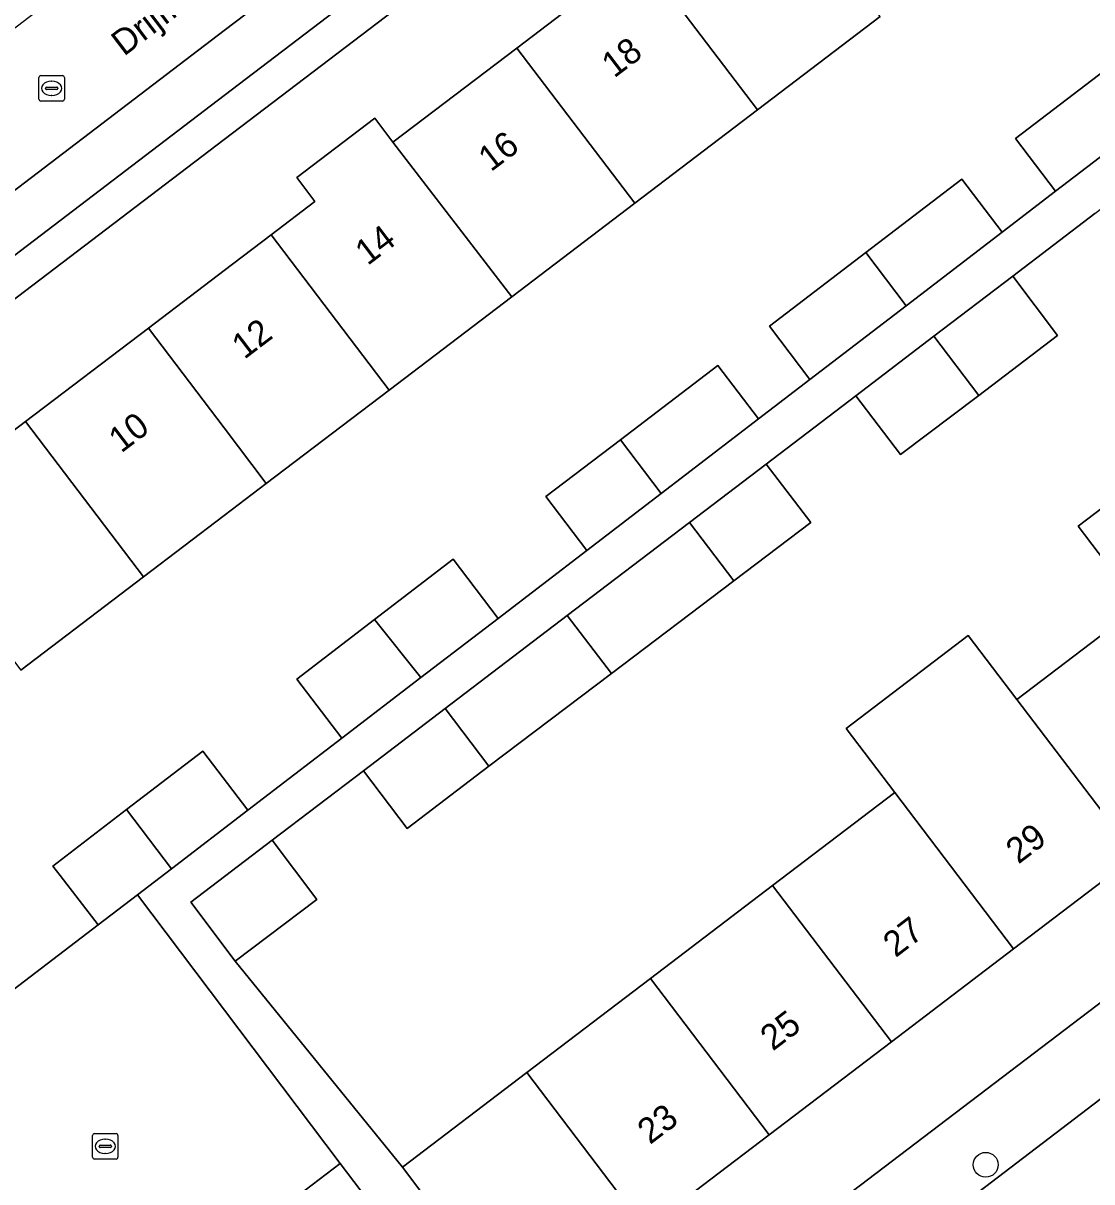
# Model space of a CAD drawing. Extents: x 160030 to 160839, y 385325 to 386450.
# Drawn here: x 160492.09 to 160534.15, y 385571 to 385616.57 of the extents above; entities that cross this region are included whole.
import ezdxf

# ---------------------------------------------------------------- set-up
doc = ezdxf.new("R2010")
doc.units = 0
for name, color, linetype in [('IMGEO_Boom', 7, 'Continuous'), ('IMGEO_Erf', 7, 'Continuous'), ('IMGEO_Kolk', 7, 'Continuous'), ('IMGEO_Openbare_ruimte_label', 7, 'Continuous'), ('IMGEO_Pand', 7, 'Continuous'), ('IMGEO_Pand_nummerreeks', 7, 'Continuous'), ('IMGEO_Parkeervlak_open', 7, 'Continuous'), ('IMGEO_Rijbaan_lokaal_open', 7, 'Continuous'), ('IMGEO_Rioolput', 7, 'Continuous'), ('IMGEO_Voetpad_open', 7, 'Continuous')]:
    doc.layers.add(name, color=color, linetype=linetype)

msp = doc.modelspace()

# ---------------------------------------------------------------- linework, layer by layer
at = {"layer": 'IMGEO_Boom'}
msp.add_circle((160529.975, 385571.672), 0.489, dxfattribs=at)
at = {"layer": 'IMGEO_Erf'}
for points in [[(160541.325, 385643.407), (160500, 385611.993), (160469.864, 385589.083), (160469.192, 385588.563), (160476.184, 385579.322), (160477.257, 385580.137), (160472.72, 385586.106), (160477.69, 385589.884), (160482.522, 385593.557), (160487.355, 385597.231), (160492.187, 385600.904), (160497.019, 385604.577), (160500, 385606.843), (160501.851, 385608.25), (160503.572, 385609.559), (160502.858, 385610.499)], [(160502.858, 385610.499), (160505.931, 385612.834), (160506.645, 385611.894), (160511.516, 385615.597), (160516.348, 385619.269), (160521.179, 385622.942), (160526.011, 385626.615), (160530.844, 385630.288), (160535.676, 385633.961), (160540.508, 385637.635), (160545.479, 385641.413), (160544.268, 385643.006)], [(160525.822, 385616.835), (160520.99, 385613.162), (160516.159, 385609.489), (160511.325, 385605.815), (160506.493, 385602.142), (160501.661, 385598.469), (160500, 385597.206), (160496.829, 385594.796), (160491.998, 385591.123)], [(160482.263, 385571.356), (160495.041, 385581.104), (160493.552, 385583.047), (160493.265, 385583.423), (160496.164, 385585.643), (160499.159, 385587.937), (160500.935, 385585.618), (160504.634, 385588.451), (160502.866, 385590.777), (160505.923, 385593.12), (160509.014, 385595.487), (160510.782, 385593.16), (160514.273, 385595.834), (160512.66, 385597.951), (160515.599, 385600.191), (160519.43, 385603.113), (160521.029, 385601.009), (160523.056, 385602.561), (160521.461, 385604.66), (160525.254, 385607.552), (160529.039, 385610.438), (160530.622, 385608.356), (160532.724, 385609.966), (160531.145, 385612.043), (160534.909, 385614.912)], [(160570.612, 385608.202), (160569.688, 385609.54), (160564.787, 385605.812), (160559.929, 385602.117), (160555.119, 385598.458), (160550.31, 385594.8), (160545.5, 385591.141), (160540.691, 385587.483), (160535.881, 385583.825), (160531.071, 385580.166), (160526.262, 385576.508), (160521.452, 385572.849), (160516.589, 385569.15), (160511.694, 385565.427), (160512.156, 385564.786)], [(160534.274, 385609.084), (160531.036, 385606.619), (160532.803, 385604.284), (160529.7, 385601.935), (160526.619, 385599.603), (160524.859, 385601.917), (160521.334, 385599.235), (160523.087, 385596.929), (160520.062, 385594.64), (160515.244, 385590.994), (160510.425, 385587.346), (160507.199, 385584.905), (160505.485, 385587.171), (160501.891, 385584.435), (160503.652, 385582.103), (160500.441, 385579.678), (160507.017, 385571.576), (160511.909, 385575.297), (160516.775, 385578.998), (160521.585, 385582.657), (160526.394, 385586.315), (160524.478, 385588.835), (160529.288, 385592.493), (160531.204, 385589.974), (160536.014, 385593.633), (160533.612, 385596.792), (160538.421, 385600.449)], [(160516.064, 385564.038), (160542.084, 385583.823), (160548.164, 385588.386)]]:
    msp.add_lwpolyline(points, dxfattribs=at)
at = {"layer": 'IMGEO_Kolk'}
for p, q in [((160494.823, 385571.974), (160494.823, 385572.826)), ((160494.898, 385572.9), (160495.75, 385572.9)), ((160495.311, 385572.68), (160495.336, 385572.68)), ((160495.824, 385572.826), (160495.824, 385571.974)), ((160495.082, 385572.394), (160495.082, 385572.406)), ((160495.52, 385572.357), (160495.122, 385572.357)), ((160495.125, 385572.443), (160495.523, 385572.443)), ((160495.566, 385572.406), (160495.566, 385572.394)), ((160495.75, 385571.9), (160494.898, 385571.9)), ((160495.334, 385572.12), (160495.309, 385572.12))]:
    msp.add_line(p, q, dxfattribs=at)
for points in [[(160494.823, 385571.974), (160494.823, 385572.826)], [(160494.898, 385572.9), (160495.75, 385572.9)], [(160495.824, 385572.826), (160495.824, 385571.974)], [(160495.75, 385571.9), (160494.898, 385571.9)]]:
    msp.add_lwpolyline(points, dxfattribs=at)
for centre, radius, start, end in [((160494.9, 385572.824), 0.0765, 91.552, 178.448), ((160494.9, 385572.824), 0.0765, 91.552, 178.448), ((160495.748, 385572.824), 0.0765, 1.552, 88.448), ((160495.748, 385572.824), 0.0765, 1.552, 88.448), ((160495.122, 385572.403), 0.0403, 85.8775, 175.7526), ((160495.119, 385572.393), 0.0366, 178.938, 274.7102), ((160495.523, 385572.4), 0.043, 264.8664, 352.4533), ((160495.527, 385572.405), 0.0386, 1.7309, 96.639), ((160494.9, 385571.976), 0.0765, 181.552, 268.448), ((160494.9, 385571.976), 0.0765, 181.552, 268.448), ((160495.748, 385571.976), 0.0765, 271.552, 358.448), ((160495.748, 385571.976), 0.0765, 271.552, 358.448)]:
    msp.add_arc(centre, radius, start, end, dxfattribs=at)
for centre, major_axis, ratio, start_param, end_param in [((160495.31, 385572.4), (-0.387, 0.002), 0.722429, 4.712389, 7.853982), ((160495.335, 385572.4), (-0.39, 0.002), 0.717154, 1.570796, 4.712389)]:
    msp.add_ellipse(centre, major_axis=major_axis, ratio=ratio, start_param=start_param, end_param=end_param, dxfattribs=at)
at = {"layer": 'IMGEO_Pand'}
for points in [[(160521.179, 385622.942), (160516.348, 385619.269), (160520.99, 385613.162), (160525.822, 385616.835)], [(160516.348, 385619.269), (160511.516, 385615.597), (160516.159, 385609.489), (160520.99, 385613.162)], [(160511.325, 385605.815), (160516.159, 385609.489), (160511.516, 385615.597), (160506.645, 385611.894)], [(160536.481, 385612.843), (160534.909, 385614.912), (160531.145, 385612.043), (160532.724, 385609.966)], [(160506.645, 385611.894), (160505.931, 385612.834), (160502.858, 385610.499), (160503.572, 385609.559), (160501.851, 385608.25), (160506.493, 385602.142), (160511.325, 385605.815)], [(160530.622, 385608.356), (160529.039, 385610.438), (160525.254, 385607.552), (160526.843, 385605.462)], [(160501.851, 385608.25), (160500, 385606.843), (160497.019, 385604.577), (160500, 385600.654), (160501.661, 385598.469), (160506.493, 385602.142)], [(160526.843, 385605.462), (160525.254, 385607.552), (160521.461, 385604.66), (160523.056, 385602.561)], [(160531.036, 385606.619), (160527.933, 385604.258), (160529.7, 385601.935), (160532.803, 385604.284)], [(160496.829, 385594.796), (160500, 385597.206), (160501.661, 385598.469), (160500, 385600.654), (160497.019, 385604.577), (160492.187, 385600.904)], [(160529.7, 385601.935), (160527.933, 385604.258), (160524.859, 385601.917), (160526.619, 385599.603)], [(160521.029, 385601.009), (160519.43, 385603.113), (160515.599, 385600.191), (160517.204, 385598.079)], [(160492.187, 385600.904), (160487.355, 385597.231), (160491.998, 385591.123), (160496.829, 385594.796)], [(160538.421, 385600.449), (160533.612, 385596.792), (160536.014, 385593.633), (160540.691, 385587.483), (160545.5, 385591.141), (160540.823, 385597.291)], [(160517.204, 385598.079), (160515.599, 385600.191), (160512.66, 385597.951), (160514.273, 385595.834)], [(160521.334, 385599.235), (160518.315, 385596.937), (160520.062, 385594.64), (160523.087, 385596.929)], [(160520.062, 385594.64), (160518.315, 385596.937), (160513.507, 385593.277), (160515.244, 385590.994)], [(160510.782, 385593.16), (160509.014, 385595.487), (160505.923, 385593.12), (160507.745, 385590.834)], [(160535.881, 385583.825), (160540.691, 385587.483), (160536.014, 385593.633), (160531.204, 385589.974)], [(160515.244, 385590.994), (160513.507, 385593.277), (160508.698, 385589.616), (160510.425, 385587.346)], [(160507.745, 385590.834), (160505.923, 385593.12), (160502.866, 385590.777), (160504.634, 385588.451)], [(160529.288, 385592.493), (160524.478, 385588.835), (160526.394, 385586.315), (160531.071, 385580.166), (160535.881, 385583.825), (160531.204, 385589.974)], [(160510.425, 385587.346), (160508.698, 385589.616), (160505.485, 385587.171), (160507.199, 385584.905)], [(160500.935, 385585.618), (160499.159, 385587.937), (160496.164, 385585.643), (160497.932, 385583.318)], [(160526.394, 385586.315), (160521.585, 385582.657), (160526.262, 385576.508), (160531.071, 385580.166)], [(160497.932, 385583.318), (160496.164, 385585.643), (160493.265, 385583.423), (160493.552, 385583.047), (160495.041, 385581.104), (160496.589, 385582.29)], [(160501.891, 385584.435), (160498.69, 385581.999), (160500.441, 385579.678), (160503.652, 385582.103)], [(160521.452, 385572.849), (160526.262, 385576.508), (160521.585, 385582.657), (160516.775, 385578.998)], [(160516.775, 385578.998), (160511.909, 385575.297), (160516.589, 385569.15), (160521.452, 385572.849)], [(160511.694, 385565.427), (160516.589, 385569.15), (160511.909, 385575.297), (160507.017, 385571.576), (160508.667, 385569.406), (160509.95, 385567.72)], [(160508.463, 385566.591), (160504.567, 385571.72), (160502.091, 385569.839), (160505.987, 385564.71)]]:
    msp.add_lwpolyline(points, close=True, dxfattribs=at)
at = {"layer": 'IMGEO_Parkeervlak_open'}
for points in [[(160535.493, 385643.286), (160524.659, 385635.077), (160514.016, 385626.96), (160511.805, 385625.275), (160505.852, 385620.735), (160500, 385616.279), (160483.774, 385603.922), (160477.533, 385599.159)], [(160481.463, 385599.602), (160485.006, 385602.306), (160500, 385613.725), (160534.027, 385639.635)]]:
    msp.add_lwpolyline(points, dxfattribs=at)
at = {"layer": 'IMGEO_Rijbaan_lokaal_open'}
for points in [[(160471.301, 385594.403), (160477.533, 385599.159), (160483.774, 385603.922), (160500, 385616.279), (160505.852, 385620.735), (160511.805, 385625.275), (160508.738, 385629.311), (160500, 385622.665), (160495.185, 385619.002), (160471.728, 385601.112), (160468.226, 385598.433)], [(160504.567, 385571.72), (160496.589, 385582.29), (160495.041, 385581.104), (160482.263, 385571.356), (160478.458, 385576.33), (160476.184, 385579.322), (160469.192, 385588.563), (160466.255, 385586.22), (160472.748, 385577.368), (160487.233, 385558.552), (160489.709, 385560.433), (160492.186, 385562.314), (160494.662, 385564.196), (160497.138, 385566.077), (160499.614, 385567.958), (160500, 385568.251), (160502.091, 385569.839)]]:
    msp.add_lwpolyline(points, close=True, dxfattribs=at)
msp.add_lwpolyline([(160530.019, 385564.617), (160531.044, 385565.332), (160537.348, 385570.24), (160538.821, 385571.329), (160539.29, 385571.676), (160536.236, 385575.591), (160524.668, 385566.762)], dxfattribs=at)
at = {"layer": 'IMGEO_Rioolput'}
for p, q in [((160492.713, 385613.584), (160492.713, 385614.436)), ((160492.788, 385614.51), (160493.64, 385614.51)), ((160493.201, 385614.29), (160493.226, 385614.29)), ((160493.714, 385614.436), (160493.714, 385613.584)), ((160492.972, 385614.004), (160492.972, 385614.016)), ((160493.41, 385613.967), (160493.012, 385613.967)), ((160493.015, 385614.053), (160493.413, 385614.053)), ((160493.224, 385613.73), (160493.199, 385613.73)), ((160493.456, 385614.016), (160493.456, 385614.004)), ((160493.64, 385613.51), (160492.788, 385613.51))]:
    msp.add_line(p, q, dxfattribs=at)
for points in [[(160492.713, 385613.584), (160492.713, 385614.436)], [(160492.788, 385614.51), (160493.64, 385614.51)], [(160493.714, 385614.436), (160493.714, 385613.584)], [(160493.64, 385613.51), (160492.788, 385613.51)]]:
    msp.add_lwpolyline(points, dxfattribs=at)
for centre, radius, start, end in [((160492.79, 385614.434), 0.0765, 91.552, 178.448), ((160492.79, 385614.434), 0.0765, 91.552, 178.448), ((160493.638, 385614.434), 0.0765, 1.552, 88.448), ((160493.638, 385614.434), 0.0765, 1.552, 88.448), ((160493.012, 385614.013), 0.0403, 85.8775, 175.7526), ((160493.009, 385614.003), 0.0366, 178.938, 274.7102), ((160493.413, 385614.01), 0.043, 264.8664, 352.4533), ((160493.417, 385614.015), 0.0386, 1.7309, 96.639), ((160492.79, 385613.586), 0.0765, 181.552, 268.448), ((160492.79, 385613.586), 0.0765, 181.552, 268.448), ((160493.638, 385613.586), 0.0765, 271.552, 358.448), ((160493.638, 385613.586), 0.0765, 271.552, 358.448)]:
    msp.add_arc(centre, radius, start, end, dxfattribs=at)
for centre, major_axis, ratio, start_param, end_param in [((160493.2, 385614.01), (-0.387, 0.002), 0.722429, 4.712389, 7.853982), ((160493.225, 385614.01), (-0.39, 0.002), 0.717154, 1.570796, 4.712389)]:
    msp.add_ellipse(centre, major_axis=major_axis, ratio=ratio, start_param=start_param, end_param=end_param, dxfattribs=at)
at = {"layer": 'IMGEO_Voetpad_open'}
for points in [[(160477.533, 385599.159), (160471.301, 385594.403), (160469.139, 385592.753), (160467.641, 385591.609), (160469.864, 385589.083), (160500, 385611.993), (160541.325, 385643.407)], [(160534.027, 385639.635), (160500, 385613.725), (160485.006, 385602.306), (160481.463, 385599.602)], [(160508.667, 385569.406), (160507.017, 385571.576), (160500.441, 385579.678), (160498.69, 385581.999), (160501.891, 385584.435), (160505.485, 385587.171), (160508.698, 385589.616), (160513.507, 385593.277), (160518.315, 385596.937), (160521.334, 385599.235), (160524.859, 385601.917), (160527.933, 385604.258), (160531.036, 385606.619), (160534.274, 385609.084), (160537.549, 385611.577), (160540.501, 385613.824), (160543.365, 385616.004), (160547.12, 385618.958)], [(160543.17, 385617.737), (160539.678, 385615.292), (160536.481, 385612.843), (160532.724, 385609.966), (160530.622, 385608.356), (160526.843, 385605.462), (160523.056, 385602.561), (160521.029, 385601.009), (160517.204, 385598.079), (160514.273, 385595.834), (160510.782, 385593.16), (160507.745, 385590.834), (160504.634, 385588.451), (160500.935, 385585.618), (160497.932, 385583.318), (160496.589, 385582.29), (160504.567, 385571.72), (160508.463, 385566.591)], [(160569.788, 385604.966), (160548.164, 385588.386), (160542.084, 385583.823), (160516.064, 385564.038)], [(160524.668, 385566.762), (160536.236, 385575.591)]]:
    msp.add_lwpolyline(points, dxfattribs=at)

# ---------------------------------------------------------------- texts
at = {"layer": 'IMGEO_Openbare_ruimte_label'}
msp.add_text('Drijffhoutstraat', height=1, rotation=37.317, dxfattribs=at).set_placement((160496.058, 385615.248))
at = {"layer": 'IMGEO_Pand_nummerreeks'}
for s, rotation, p in [('18', 37.2399, (160515.351, 385614.392)), ('16', 37.2399, (160510.498, 385610.703)), ('14', 37.2399, (160505.648, 385607.016)), ('12', 37.2399, (160500.795, 385603.327)), ('10', 37.2399, (160495.949, 385599.643)), ('29', 37.2583, (160531.259, 385583.475)), ('27', 37.2583, (160526.426, 385579.798)), ('25', 37.2583, (160521.593, 385576.122)), ('23', 37.2583, (160516.761, 385572.446))]:
    msp.add_text(s, height=1, rotation=rotation, dxfattribs=at).set_placement(p)

doc.saveas('drawing.dxf')
